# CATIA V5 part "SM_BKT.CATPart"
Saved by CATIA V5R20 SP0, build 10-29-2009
Part number: SM_BKT
Bounding box of the stored display mesh (mm): x 0 to 120.298, y -20 to 275, z 0 to 25
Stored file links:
  C:\Users\CAS\Desktop\GSD_Class_Parts\SM_BKT.CATPart
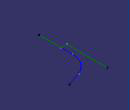
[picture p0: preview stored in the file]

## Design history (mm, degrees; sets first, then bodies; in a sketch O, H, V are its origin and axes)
Set1 "CONST_GEO"
  Point1: type OnCurve, Support Sketch1, Length 10
Set2 "Inputs"
  Sketch1 "Flange Sketch" on xy-plane, origin (0, 0, 0), H (1, 0, 0), V (0, 1, 0)
    point P1 (0, -20)
    line L1 (0, -20) -> (0, 125)
    arc A1 centre (90, 125) radius 90 from (0, 125) to (59.2182, 209.5723) cw
    point P3 (90, 125)
    line L2 (59.2182, 209.5723) -> (120.2982, 231.8036)
    radius A1 = 90
    distance H P3 = 125
    angle L1 L2 = 110
    length L2 = 65
    distance H P1 = 20
    coincidence: P1 V
    vertical: L1 V
    tangency: A1 L1, A1 L2
  Sketch2 "Main Body Sketch" on yz-plane, origin (0, 0, 0), H (0, 1, 0), V (0, 0, 1)
    point P1 (-20, 0)
    line L1 (-20, 0) -> (75, 0)
    point P2 (75, 0)
    line L2 (75, 0) -> (100, 25)
    line L3 (100, 25) -> (275, 25)
    reference intersected line E1 through (0, 0) direction (0, 1) from zx-plane
    distance V P1 = 20
    angle L1 L2 = 45
    distance L1 L3 = 25
    distance E1 P2 = 75
    length L3 = 175
    horizontal: L1 H, L3 H
    coincidence: H L1
Set3 "Spliting Elements"
  Plane1: type Normal, Curve Sketch1, RefPoint Point1
Body1 (main body)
